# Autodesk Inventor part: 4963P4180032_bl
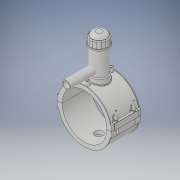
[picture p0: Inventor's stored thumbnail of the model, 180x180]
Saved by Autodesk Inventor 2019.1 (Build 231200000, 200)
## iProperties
Created: 2017-07
Part Number: 4963P4180032_bl
Material: Generic
Document SubType Name: Modeling
Designer: KIM
Density: 1 g/cm^3
Appearance: Default
Author: KIM
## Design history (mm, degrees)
derived "4963P4.ipt"
feature "Solid1::4963P4.ipt" dims "ScaleForDerivedMember" = 10
feature "Solid2::4963P4.ipt" dims "ScaleForDerivedMember" = 10
feature "Solid3::4963P4.ipt" dims "ScaleForDerivedMember" = 10
tag "TaggingFeature1"
body "Solid1"
body "Solid2"
body "Solid3"
other parameters: "d2" = 219 [user parameter], "d3" = 45 [user parameter], "d4" = 118 [user parameter], "d5" = 0 [user parameter], "d6" = 0.1 [user parameter], "d8" = 0 [user parameter], "d19" = 6 [user parameter], "d20" = 6 [user parameter], "d21" = 70.8 [user parameter], "d23" = 0 [user parameter], "d24" = 35.4 [user parameter], "d26" = 0 [user parameter], "d27" = 3 [user parameter], "d28" = 3 [user parameter], "d29" = 3 [user parameter], "d31" = 6 [user parameter], "d32" = 0 [user parameter], "d33" = 0 [user parameter], "d34" = 0.6 [user parameter], "d40" = 108.576 [user parameter], "d41" = 72 [user parameter], "d43" = 0 [user parameter], "d45" = 0 [user parameter], "d47" = 175.2 [user parameter], "d70" = 15 [user parameter], "d72" = 0 [user parameter], "d73" = 6 [user parameter], "d75" = 5 [user parameter], "d76" = 0 [user parameter], "d77" = 9 [user parameter], "d79" = 15 [user parameter], "d80" = 47.2 [user parameter], "d82" = 5 deg [user parameter], "d84" = 4 [user parameter], "d85" = 14 [user parameter], "d86" = 0 [user parameter], "d87" = 3 [user parameter], "d88" = 0 [user parameter], "d89" = 1 [user parameter], "d90" = 1 [user parameter], "d91" = 94.4 [user parameter], "d92" = 0 [user parameter], "d93" = 0.5 [user parameter], "d94" = 94.73684 [user parameter], "d96" = 212.976 [user parameter], "d97" = 2.36 [user parameter], "d98" = 0 [user parameter], "d102" = 1.8 [user parameter], "d120" = 140 deg [user parameter], "d121" = 24.228 [user parameter], "d122" = 20 deg [user parameter], "d123" = 417.6 [user parameter], "d124" = 125.28 [user parameter], "d126" = 0 [user parameter], "d143" = 185.4 [user parameter], "d145" = 22.15385 [user parameter], "d149" = 2.7 [user parameter], "d150" = 24.36923 [user parameter], "d153" = 118 [user parameter], "d154" = 0 [user parameter], "d156" = 104.4 [user parameter], "d157" = 160 deg [user parameter], "d159" = 5.76 [user parameter], "d161" = 2.7 [user parameter], "d162" = 70.8 [user parameter], "d163" = 0 [user parameter], "d167" = 18 [user parameter], "d168" = 101.85366 [user parameter], "d170" = 3.75 [user parameter], "d172" = 0 [user parameter], "d173" = 1 [user parameter], "d176" = 20 deg [user parameter], "d177" = 12.6 [user parameter], "d178" = 28.8 [user parameter], "d180" = 0 [user parameter], "d183" = 11.52 [user parameter], "d184" = 10.08 [user parameter], "d185" = 38.35 [user parameter], "d186" = 38.35 [user parameter], "d187" = 104.4 [user parameter], "d188" = 8.64 [user parameter], "d189" = 12.6 [user parameter], "d190" = 0 [user parameter], "d191" = 156.6 [user parameter], "d193" = 8 [user parameter], "d194" = 4.13 [user parameter], "d195" = 90 deg [user parameter], "d197" = 0 [user parameter], "d199" = 0 [user parameter], "d200" = 14.4 [user parameter], "d202" = 0 [user parameter], "d203" = 177 [user parameter], "d204" = 68.4 [user parameter], "d205" = 50.4 [user parameter], "d206" = 61.2 [user parameter], "d207" = 132.75 [user parameter], "d208" = 138.06 [user parameter], "d209" = 164.61 [user parameter], "d210" = 61.92 [user parameter], "d211" = 72 [user parameter], "d212" = 57.6 [user parameter], "d213" = 36 [user parameter], "d216" = 0 [user parameter], "d217" = 18 [user parameter], "d218" = 18 [user parameter], "d219" = 3.6 [user parameter], "d224" = 0 [user parameter], "d225" = 56 [user parameter], "d226" = 32 [user parameter], "d227" = 25.6 [user parameter], "d228" = 132 [user parameter], "d230" = 3.6 [user parameter], "B_" = 219 [user parameter], "L_" = 118 [user parameter], "d_t" = 6 [user parameter], "H_2" = 177 [user parameter], "H_1" = 56 [user parameter], "d_1" = 32 [user parameter], "H_" = 132 [user parameter], "d1" = 208.8 [user parameter]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
